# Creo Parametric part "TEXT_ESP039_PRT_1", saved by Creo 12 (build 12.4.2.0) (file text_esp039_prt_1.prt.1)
Units: Custom; MM, KILOGRAM, SECS

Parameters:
  PTC_WM_ITERATION = "0"
  PTC_WM_VERSION = "-.0"
  PTC_WM_LIFECYCLE_STATE = "In Work"
  PTC_WM_LIFECYCLE = "MO_CADDocument"
  PTC_WM_CREATED_BY = "Maximilian Roepper (Z0017RMS: MO)"
  PTC_WM_CREATED_ON = "18-Sep-26 11:36:42 AM"
  PTC_WM_MODIFIED_BY = "Maximilian Roepper (Z0017RMS: MO)"
  PTC_WM_MODIFIED_ON = "18-Sep-26 11:36:46 AM"
  PDMLINKNUMBER = "PDM000071455114"
  PTC_WM_NAME = "text_esp039_prt_1.prt"
  PTC_WM_NUMBER = "PDM000071455114"

Other parameters: WEIGHT, WEIGHT_FACTOR, WEIGHT_ADD, _MASS_TEMP, _DIFF_TEMP, MC_ERRORS, SUPPLIER

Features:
  1. coordinate system
  2. datum plane "PRT_YZ"
  3. datum plane "PRT_XY"
  4. datum plane "PRT_XZ"
  5. coordinate system
  6. datum axis
  7. datum axis
  8. datum axis
  9. coordinate system
  10. imported feature
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
Other named items: PRT, SIEMENS_MO, DRW_VIEW_ORG, PRT_X, PRT_Y, PRT_Z, CS0, ROUGH_GROB

Layers: 00_STD_CSYS-KSYS, 01_STD_PLANES-EBENEN, 02_STD_AXES-ACHSEN, 03_STD_CSYS-KSYS, 24_IMPORT_FEAT-IMPORT_KE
